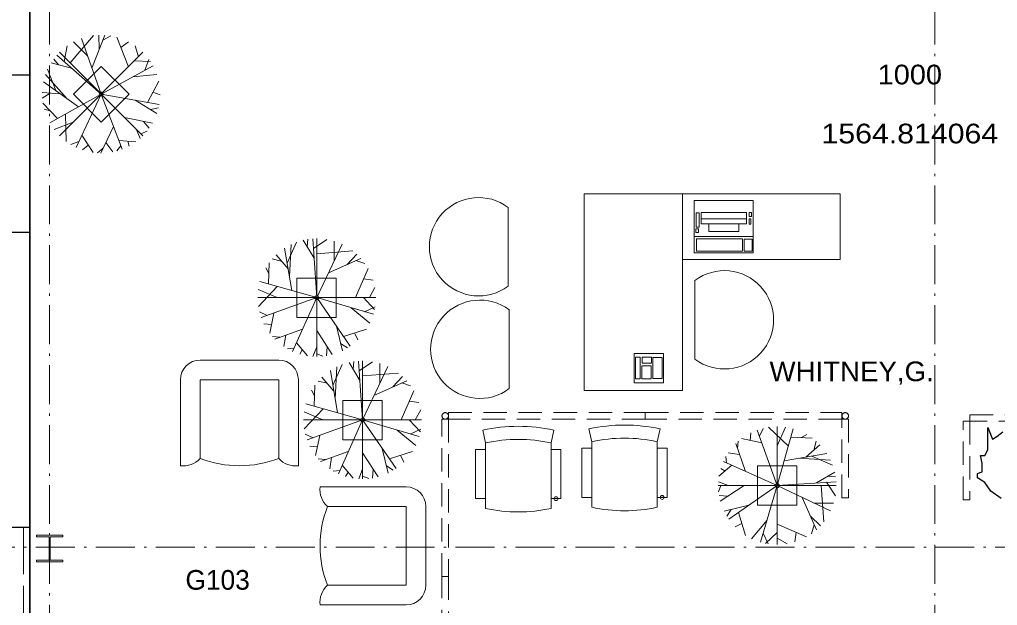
# Model space of a CAD drawing. Extents: x -118748 to -117136, y -118748 to -117596.
# Drawn here: x -118499.3 to -118260.7, y -118199 to -118056 of the extents above; entities that cross this region are included whole.
import ezdxf
from ezdxf.enums import TextEntityAlignment as Align

# ---------------------------------------------------------------- set-up
doc = ezdxf.new("R2010")
doc.units = 0
doc.header["$LTSCALE"] = 1.9
doc.header["$PDMODE"] = 32
doc.header["$PDSIZE"] = 0.95
for name, pattern in [('DOT_DASHED', [7.7, 5, -1.2, 0.3, -1.2]), ('LONG_DASHED', [7.5, 6, -1.5]), ('MEDIUM_DASHED', [4.5, 3, -1.5])]:
    doc.linetypes.add(name, pattern=pattern)
for name, color, linetype, lineweight in [('10', 7, 'DOT_DASHED', 13), ('12', 7, 'Continuous', 13), ('15', 7, 'Continuous', 13), ('16', 7, 'Continuous', 13), ('17', 7, 'Continuous', 25), ('20', 7, 'MEDIUM_DASHED', 13), ('23', 7, 'Continuous', 25), ('30', 7, 'Continuous', 13), ('4', 7, 'Continuous', 35), ('45', 7, 'Continuous', 25), ('5', 7, 'Continuous', 13), ('6', 7, 'Continuous', 13), ('60', 7, 'LONG_DASHED', 13), ('9', 7, 'Continuous', 35)]:
    doc.layers.add(name, color=color, linetype=linetype, lineweight=lineweight)
doc.layers.add('53', color=7, linetype='Continuous')

msp = doc.modelspace()

# ---------------------------------------------------------------- linework, layer by layer
at = {"layer": '10'}
for p, q in [((-118491.921, -117628.339), (-118491.921, -118698.41)), ((-118275.921, -117628.339), (-118275.921, -118698.41)), ((-118641.571, -118184.81), (-117285.521, -118184.81))]:
    msp.add_line(p, q, dxfattribs=at)
at = {"layer": '12'}
msp.add_lwpolyline([(-118495.104, -118188.362), (-118488.688, -118188.362), (-118488.688, -118187.966), (-118491.772, -118187.966), (-118491.772, -118182.262), (-118488.688, -118182.262), (-118488.688, -118181.866), (-118495.104, -118181.866), (-118495.104, -118182.262), (-118492.02, -118182.262), (-118492.02, -118187.966), (-118495.104, -118187.966)], close=True, dxfattribs=at)
at = {"layer": '15', "lineweight": 25}
for p, q in [((-118496.721, -118031.21), (-118496.721, -118069.61)), ((-118496.721, -118069.61), (-118506.321, -118069.61)), ((-118496.721, -118108.01), (-118506.321, -118108.01)), ((-118496.721, -118108.01), (-118496.721, -118180.01)), ((-118496.721, -118180.01), (-118586.321, -118180.01))]:
    msp.add_line(p, q, dxfattribs=at)
at = {"layer": '15'}
for p, q in [((-118380.049, -118101.88), (-118380.049, -118121.08)), ((-118334.488, -118138.921), (-118334.488, -118119.721)), ((-118379.768, -118126.911), (-118379.768, -118146.111)), ((-118436.026, -118139.148), (-118455.226, -118139.148)), ((-118460.026, -118143.948), (-118460.026, -118164.933)), ((-118431.226, -118164.933), (-118431.226, -118143.948)), ((-118385.586, -118159.364), (-118386.262, -118156.236)), ((-118369.586, -118159.364), (-118368.91, -118156.236)), ((-118359.666, -118159.062), (-118360.342, -118155.934)), ((-118343.666, -118159.062), (-118342.99, -118155.934)), ((-118385.586, -118175.364), (-118385.586, -118159.364)), ((-118369.586, -118175.364), (-118369.586, -118159.364)), ((-118359.666, -118175.062), (-118359.666, -118159.062)), ((-118343.666, -118175.062), (-118343.666, -118159.062)), ((-118387.986, -118172.964), (-118387.986, -118160.964)), ((-118385.586, -118160.964), (-118387.986, -118160.964)), ((-118385.586, -118172.964), (-118385.586, -118160.964)), ((-118369.586, -118172.964), (-118369.586, -118160.964)), ((-118367.186, -118160.964), (-118369.586, -118160.964)), ((-118367.186, -118172.964), (-118367.186, -118160.964)), ((-118362.066, -118172.662), (-118362.066, -118160.662)), ((-118359.666, -118160.662), (-118362.066, -118160.662)), ((-118359.666, -118172.662), (-118359.666, -118160.662)), ((-118343.666, -118172.662), (-118343.666, -118160.662)), ((-118341.266, -118160.662), (-118343.666, -118160.662)), ((-118341.266, -118172.662), (-118341.266, -118160.662)), ((-118404.942, -118170.1), (-118425.928, -118170.1)), ((-118387.986, -118172.964), (-118385.586, -118172.964)), ((-118369.586, -118172.964), (-118367.186, -118172.964)), ((-118362.066, -118172.662), (-118359.666, -118172.662)), ((-118343.666, -118172.662), (-118341.266, -118172.662)), ((-118400.142, -118194.1), (-118400.142, -118174.899)), ((-118425.928, -118198.899), (-118404.942, -118198.899))]:
    msp.add_line(p, q, dxfattribs=at)
for points in [[(-118361.487, -118146.556), (-118361.487, -118098.556), (-118337.487, -118098.556), (-118337.487, -118146.556)], [(-118337.487, -118114.556), (-118337.487, -118098.556), (-118299.087, -118098.556), (-118299.087, -118114.556)]]:
    msp.add_lwpolyline(points, close=True, dxfattribs=at)
for points in [[(-118436.026, -118163.148), (-118436.026, -118143.948), (-118455.226, -118143.948), (-118455.226, -118163.148)], [(-118424.142, -118194.1), (-118404.942, -118194.1), (-118404.942, -118174.899), (-118424.142, -118174.899)]]:
    msp.add_lwpolyline(points, dxfattribs=at)
for centre, radius, start, end in [((-118387.249, -118111.48), 12, 53.1301, 306.86989), ((-118327.288, -118129.321), 12, 233.1301, 126.86989), ((-118386.968, -118136.511), 12, 53.1301, 306.86989), ((-118455.226, -118143.948), 4.8, 90, 180), ((-118436.026, -118143.948), 4.8, 0, 90), ((-118351.666, -118196.07), 41.063, 77.80217, 102.19783), ((-118377.586, -118196.372), 41.063, 77.80217, 102.19783), ((-118377.586, -118196.372), 37.863, 77.80217, 102.19783), ((-118377.586, -118196.372), 37.863, 77.80217, 102.19783), ((-118351.666, -118196.07), 37.863, 77.80217, 102.19783), ((-118351.666, -118196.07), 37.863, 77.80217, 102.19783), ((-118459.331, -118159.456), 5.521, 262.77334, 318.03706), ((-118445.626, -118138.234), 26.699, 248.92678, 291.07322), ((-118431.92, -118159.456), 5.521, 221.96294, 277.22666), ((-118420.451, -118170.794), 5.521, 172.77334, 228.03706), ((-118404.942, -118174.899), 4.8, 0, 90), ((-118399.229, -118184.5), 26.699, 158.92678, 201.07322), ((-118377.586, -118138.355), 37.863, 257.80217, 282.19783), ((-118351.666, -118138.054), 37.863, 257.80217, 282.19783), ((-118420.451, -118198.205), 5.521, 131.96294, 187.22666), ((-118404.942, -118194.1), 4.8, 270, 0)]:
    msp.add_arc(centre, radius, start, end, dxfattribs=at)
for p in [(-118368.386, -118172.964), (-118342.466, -118172.662)]:
    msp.add_point(p, dxfattribs=at)
at = {"layer": '16'}
for p, q in [((-118496.721, -118069.61), (-118496.721, -118108.01)), ((-118334.638, -118109.006), (-118320.238, -118109.006))]:
    msp.add_line(p, q, dxfattribs=at)
for points in [[(-118334.638, -118113.006), (-118334.638, -118100.206), (-118320.238, -118100.206), (-118320.238, -118113.006)], [(-118334.18, -118106.724), (-118334.18, -118103.187), (-118333.473, -118103.187), (-118333.473, -118106.724)], [(-118332.974, -118104.685), (-118332.974, -118103.085), (-118321.865, -118103.085), (-118321.865, -118104.685)], [(-118332.974, -118105.891), (-118332.974, -118104.685), (-118321.865, -118104.685), (-118321.865, -118105.891)], [(-118321.24, -118103.104), (-118321.24, -118104.102), (-118320.658, -118104.102), (-118320.658, -118103.104)], [(-118321.24, -118104.685), (-118321.24, -118105.933), (-118320.824, -118105.933), (-118320.824, -118104.685)], [(-118334.263, -118107.972), (-118334.263, -118107.14), (-118333.598, -118107.14), (-118333.598, -118107.972)], [(-118331.06, -118107.764), (-118331.06, -118105.891), (-118323.737, -118105.891), (-118323.737, -118107.764)], [(-118334.097, -118109.553), (-118334.097, -118112.549), (-118322.905, -118112.549), (-118322.905, -118109.553)], [(-118322.489, -118109.636), (-118322.489, -118112.59), (-118320.492, -118112.59), (-118320.492, -118109.636)], [(-118349.334, -118144.712), (-118349.334, -118137.512), (-118342.134, -118137.512), (-118342.134, -118144.712)], [(-118347.878, -118143.706), (-118347.878, -118138.464), (-118348.959, -118138.464), (-118348.959, -118143.706)], [(-118347.378, -118138.464), (-118347.378, -118139.92), (-118345.09, -118139.92), (-118345.09, -118138.464)], [(-118347.461, -118140.585), (-118347.461, -118143.706), (-118345.173, -118143.706), (-118345.173, -118140.585)], [(-118344.715, -118138.547), (-118344.715, -118143.664), (-118342.51, -118143.664), (-118342.51, -118138.547)]]:
    msp.add_lwpolyline(points, close=True, dxfattribs=at)
at = {"layer": '17'}
msp.add_lwpolyline([(-118259.734, -118172.971), (-118262.268, -118171.161), (-118263.716, -118168.989), (-118265.526, -118167.902), (-118265.526, -118166.816), (-118264.44, -118166.454), (-118264.44, -118164.282), (-118264.802, -118162.472), (-118263.716, -118162.472), (-118262.992, -118161.024), (-118262.992, -118155.593), (-118261.906, -118158.489), (-118260.82, -118157.765), (-118259.372, -118156.679)], dxfattribs=at)
at = {"layer": '20'}
for points in [[(-118394.602, -118153.574), (-118394.602, -118151.974), (-118346.602, -118151.974), (-118346.602, -118153.574)], [(-118346.602, -118153.574), (-118346.602, -118151.974), (-118298.602, -118151.974), (-118298.602, -118153.574)], [(-118229.002, -118152.479), (-118229.002, -118154.079), (-118267.402, -118154.079), (-118267.402, -118152.479)], [(-118394.602, -118191.974), (-118396.202, -118191.974), (-118396.202, -118153.574), (-118394.602, -118153.574)], [(-118298.602, -118153.574), (-118297.002, -118153.574), (-118297.002, -118172.774), (-118298.602, -118172.774)], [(-118269.002, -118154.079), (-118267.402, -118154.079), (-118267.402, -118173.279), (-118269.002, -118173.279)], [(-118394.602, -118239.974), (-118396.202, -118239.974), (-118396.202, -118191.974), (-118394.602, -118191.974)]]:
    msp.add_lwpolyline(points, close=True, dxfattribs=at)
for centre in [(-118395.402, -118152.774), (-118297.802, -118152.774)]:
    msp.add_circle(centre, 0.8, dxfattribs=at)
at = {"layer": '23'}
for q in [(-118499.921, -118180.01), (-118496.721, -118292.01)]:
    msp.add_line((-118496.721, -118180.01), q, dxfattribs=at)
at = {"layer": '30'}
for p, q in [((-118486.922, -118066.624), (-118481.183, -118059.923)), ((-118482.657, -118064.878), (-118486.066, -118061.472)), ((-118479.34, -118074.205), (-118484.164, -118060.637)), ((-118481.589, -118067.882), (-118478.486, -118059.83)), ((-118479.805, -118063.252), (-118479.895, -118059.816)), ((-118478.964, -118061.071), (-118476.961, -118060.003)), ((-118472.672, -118067.537), (-118475.508, -118060.324)), ((-118474.507, -118062.869), (-118472.638, -118061.46)), ((-118469.158, -118084.387), (-118489.523, -118064.023)), ((-118489.523, -118084.387), (-118469.158, -118064.023)), ((-118488.407, -118066.282), (-118487.633, -118062.432)), ((-118470.263, -118065.128), (-118471.029, -118062.446)), ((-118486.575, -118067.883), (-118491.578, -118066.615)), ((-118489.76, -118067.076), (-118490.931, -118065.66)), ((-118479.34, -118074.205), (-118490.184, -118064.73)), ((-118471.277, -118066.142), (-118467.312, -118066.289)), ((-118468.697, -118068.422), (-118467.691, -118065.74)), ((-118490.411, -118073.354), (-118492.408, -118068.156)), ((-118479.34, -118074.205), (-118466.687, -118067.331)), ((-118484.847, -118077.294), (-118493.427, -118071.218)), ((-118487.716, -118075.262), (-118492.934, -118069.454)), ((-118471.615, -118070.008), (-118465.742, -118069.467)), ((-118468.016, -118076.28), (-118465.284, -118071.079)), ((-118489.227, -118074.192), (-118493.736, -118073.867)), ((-118491.774, -118074.008), (-118493.706, -118075.197)), ((-118466.707, -118073.788), (-118464.941, -118074.38)), ((-118490.037, -118080.206), (-118493.57, -118076.414)), ((-118479.34, -118074.205), (-118491.899, -118081.25)), ((-118479.34, -118074.205), (-118485.466, -118087.237)), ((-118479.34, -118074.205), (-118474.226, -118087.666)), ((-118479.34, -118074.205), (-118465.176, -118076.801)), ((-118471.049, -118075.724), (-118465.748, -118078.959)), ((-118491.807, -118078.305), (-118493.257, -118077.904)), ((-118467.288, -118078.019), (-118465.348, -118077.609)), ((-118486.186, -118081.051), (-118490.839, -118082.873)), ((-118488.074, -118079.104), (-118487.894, -118085.789)), ((-118473.635, -118079.91), (-118466.836, -118081.347)), ((-118469.02, -118080.885), (-118467.606, -118082.551)), ((-118476.327, -118082.136), (-118479.441, -118088.605)), ((-118470.846, -118082.699), (-118469.842, -118085.028)), ((-118469.629, -118083.916), (-118468.143, -118083.26)), ((-118484.798, -118085.816), (-118486.779, -118086.535)), ((-118484.066, -118084.258), (-118481.319, -118088.468)), ((-118475.038, -118085.527), (-118470.899, -118085.872)), ((-118472.826, -118085.711), (-118472.534, -118086.895)), ((-118482.48, -118086.688), (-118483.894, -118087.866)), ((-118478.876, -118087.431), (-118480.278, -118088.574)), ((-118478.214, -118086.054), (-118476.536, -118088.329)), ((-118474.529, -118086.869), (-118475.543, -118088.095)), ((-118429.072, -118111.484), (-118428.899, -118109.655)), ((-118426.745, -118123.893), (-118427.713, -118109.526)), ((-118427.554, -118111.88), (-118424.284, -118109.705)), ((-118426.745, -118138.293), (-118426.745, -118109.493)), ((-118432.823, -118122.184), (-118434.594, -118111.82)), ((-118433.972, -118115.463), (-118431.708, -118110.375)), ((-118433.415, -118118.718), (-118432.998, -118110.921)), ((-118427.391, -118114.307), (-118430.031, -118109.873)), ((-118426.745, -118123.893), (-118420.563, -118110.888)), ((-118422.495, -118114.953), (-118422.498, -118110.134)), ((-118435.398, -118114.962), (-118437.605, -118114.436)), ((-118433.727, -118116.893), (-118436.686, -118113.474)), ((-118426.745, -118113.172), (-118417.95, -118112.491)), ((-118423.864, -118117.832), (-118415.977, -118114.333)), ((-118419.329, -118115.82), (-118416.963, -118113.326)), ((-118438.46, -118117.977), (-118439.202, -118116.668)), ((-118438.552, -118120.572), (-118438.369, -118115.393)), ((-118417.315, -118123.893), (-118414.22, -118116.788)), ((-118417.192, -118114.872), (-118415.02, -118115.533)), ((-118415.312, -118119.295), (-118412.994, -118119.62)), ((-118436.385, -118121.182), (-118440.985, -118126.036)), ((-118426.745, -118123.893), (-118440.608, -118119.994)), ((-118413.908, -118123.893), (-118412.553, -118121.455)), ((-118441.145, -118123.893), (-118412.345, -118123.893)), ((-118436.427, -118123.893), (-118441.005, -118121.892)), ((-118426.745, -118123.893), (-118440.292, -118128.777)), ((-118426.745, -118123.893), (-118432.647, -118137.028)), ((-118426.745, -118123.893), (-118412.937, -118127.979)), ((-118426.745, -118123.893), (-118418.565, -118135.744)), ((-118415.342, -118123.893), (-118412.642, -118126.801)), ((-118418.314, -118126.388), (-118413.78, -118130.158)), ((-118415.13, -118127.33), (-118412.522, -118126.144)), ((-118438.815, -118128.244), (-118440.724, -118127.352)), ((-118437.195, -118127.66), (-118438.23, -118132.579)), ((-118437.793, -118130.5), (-118439.625, -118130.333)), ((-118421.957, -118130.83), (-118420.495, -118136.866)), ((-118435.769, -118133.573), (-118437.569, -118133.391)), ((-118430.222, -118131.632), (-118436.999, -118134.004)), ((-118434.327, -118133.068), (-118434.749, -118135.864)), ((-118426.745, -118131.961), (-118422.953, -118137.785)), ((-118420.205, -118133.368), (-118414.595, -118131.622)), ((-118417.517, -118132.532), (-118416.688, -118134.198)), ((-118431.709, -118134.941), (-118429.026, -118138.111)), ((-118426.745, -118135.905), (-118427.682, -118138.263)), ((-118424.172, -118135.914), (-118424.349, -118138.092)), ((-118420.92, -118135.112), (-118419.258, -118136.194)), ((-118432.298, -118136.25), (-118433.882, -118136.4)), ((-118430.275, -118136.636), (-118430.906, -118137.679)), ((-118426.745, -118137.626), (-118425.23, -118138.213)), ((-118422.802, -118145.322), (-118420.538, -118140.234)), ((-118422.245, -118148.577), (-118421.828, -118140.78)), ((-118416.221, -118144.165), (-118418.861, -118139.731)), ((-118417.902, -118141.343), (-118417.729, -118139.514)), ((-118415.575, -118153.751), (-118416.543, -118139.384)), ((-118416.384, -118141.738), (-118413.114, -118139.563)), ((-118415.575, -118168.152), (-118415.575, -118139.352)), ((-118415.575, -118153.751), (-118409.393, -118140.746)), ((-118411.325, -118144.811), (-118411.328, -118139.992)), ((-118421.653, -118152.042), (-118423.424, -118141.679)), ((-118415.575, -118143.03), (-118406.78, -118142.35)), ((-118408.159, -118145.679), (-118405.793, -118143.185)), ((-118427.382, -118150.431), (-118427.199, -118145.252)), ((-118424.228, -118144.821), (-118426.435, -118144.295)), ((-118422.557, -118146.751), (-118425.516, -118143.333)), ((-118412.694, -118147.69), (-118404.807, -118144.191)), ((-118406.022, -118144.731), (-118403.85, -118145.392)), ((-118427.29, -118147.835), (-118428.032, -118146.527)), ((-118406.145, -118153.751), (-118403.05, -118146.647)), ((-118415.575, -118153.751), (-118429.438, -118149.853)), ((-118404.142, -118149.153), (-118401.824, -118149.479)), ((-118425.257, -118153.751), (-118429.836, -118151.75)), ((-118425.215, -118151.04), (-118429.815, -118155.895)), ((-118402.738, -118153.751), (-118401.383, -118151.313)), ((-118429.975, -118153.751), (-118401.175, -118153.751)), ((-118415.575, -118153.751), (-118429.122, -118158.635)), ((-118415.575, -118153.751), (-118421.477, -118166.887)), ((-118415.575, -118153.751), (-118401.767, -118157.838)), ((-118415.575, -118153.751), (-118407.395, -118165.602)), ((-118404.173, -118153.751), (-118401.472, -118156.659)), ((-118427.645, -118158.103), (-118429.554, -118157.21)), ((-118426.025, -118157.519), (-118427.06, -118162.438)), ((-118407.144, -118156.246), (-118402.61, -118160.017)), ((-118403.96, -118157.189), (-118401.352, -118156.003)), ((-118321.002, -118158.744), (-118320.835, -118156.911)), ((-118314.396, -118169.791), (-118319.279, -118156.245)), ((-118318.747, -118157.722), (-118317.854, -118155.813)), ((-118311.684, -118160.152), (-118316.539, -118155.552)), ((-118314.396, -118155.391), (-118314.396, -118184.191)), ((-118314.396, -118160.11), (-118312.394, -118155.531)), ((-118314.396, -118169.791), (-118310.497, -118155.929)), ((-118308.479, -118158.076), (-118307.171, -118157.335)), ((-118322.134, -118166.314), (-118324.506, -118159.538)), ((-118324.076, -118160.767), (-118323.893, -118158.967)), ((-118318.163, -118159.342), (-118323.082, -118158.306)), ((-118311.075, -118157.984), (-118305.896, -118158.168)), ((-118307.395, -118162.809), (-118303.977, -118159.851)), ((-118305.465, -118161.139), (-118304.939, -118158.932)), ((-118426.623, -118160.358), (-118428.455, -118160.191)), ((-118419.052, -118161.49), (-118425.829, -118163.862)), ((-118415.575, -118161.82), (-118411.783, -118167.643)), ((-118410.787, -118160.689), (-118409.325, -118166.724)), ((-118409.035, -118163.227), (-118403.425, -118161.48)), ((-118323.571, -118162.209), (-118326.366, -118161.787)), ((-118312.686, -118163.713), (-118302.323, -118161.942)), ((-118424.599, -118163.432), (-118426.399, -118163.249)), ((-118423.157, -118162.927), (-118423.579, -118165.722)), ((-118406.347, -118162.39), (-118405.518, -118164.057)), ((-118314.396, -118169.791), (-118327.531, -118163.889)), ((-118326.753, -118164.239), (-118326.903, -118162.655)), ((-118309.221, -118163.121), (-118301.424, -118163.539)), ((-118305.966, -118162.565), (-118300.878, -118164.829)), ((-118421.128, -118166.109), (-118422.712, -118166.259)), ((-118420.539, -118164.8), (-118417.856, -118167.97)), ((-118419.105, -118166.494), (-118419.736, -118167.537)), ((-118415.575, -118165.764), (-118416.512, -118168.121)), ((-118413.001, -118165.772), (-118413.179, -118167.951)), ((-118409.75, -118164.971), (-118408.088, -118166.052)), ((-118325.444, -118164.827), (-118328.614, -118167.511)), ((-118327.138, -118166.262), (-118328.182, -118165.631)), ((-118304.809, -118169.146), (-118300.376, -118166.505)), ((-118415.575, -118167.485), (-118414.06, -118168.072)), ((-118326.408, -118169.791), (-118328.765, -118168.855)), ((-118314.396, -118169.791), (-118300.028, -118168.824)), ((-118302.382, -118168.982), (-118300.208, -118172.252)), ((-118301.987, -118167.465), (-118300.158, -118167.637)), ((-118328.796, -118169.791), (-118299.996, -118169.791)), ((-118328.129, -118169.791), (-118328.716, -118171.306)), ((-118322.464, -118169.791), (-118328.287, -118173.583)), ((-118314.396, -118169.791), (-118326.247, -118177.971)), ((-118314.396, -118169.791), (-118318.482, -118183.599)), ((-118314.396, -118169.791), (-118301.39, -118175.974)), ((-118303.674, -118169.791), (-118302.994, -118178.587)), ((-118326.417, -118172.365), (-118328.595, -118172.188)), ((-118308.335, -118172.673), (-118304.836, -118180.56)), ((-118305.456, -118174.041), (-118300.636, -118174.039)), ((-118321.333, -118174.58), (-118327.369, -118176.041)), ((-118325.615, -118175.617), (-118326.696, -118177.278)), ((-118323.871, -118176.332), (-118322.124, -118181.941)), ((-118323.034, -118179.019), (-118324.701, -118179.849)), ((-118316.891, -118178.222), (-118320.661, -118182.757)), ((-118306.323, -118177.208), (-118303.829, -118179.574)), ((-118317.833, -118181.407), (-118316.647, -118184.014)), ((-118314.396, -118181.194), (-118317.304, -118183.895)), ((-118314.396, -118179.222), (-118307.291, -118182.316)), ((-118309.797, -118181.225), (-118310.123, -118183.543)), ((-118305.375, -118179.345), (-118306.036, -118181.516)), ((-118314.396, -118182.628), (-118311.957, -118183.983))]:
    msp.add_line(p, q, dxfattribs=at)
for points in [[(-118479.337, -118081.058), (-118486.125, -118074.27), (-118479.337, -118067.481), (-118472.549, -118074.27)], [(-118431.589, -118128.741), (-118431.589, -118119.141), (-118421.989, -118119.141), (-118421.989, -118128.741)], [(-118420.419, -118158.6), (-118420.419, -118149), (-118410.819, -118149), (-118410.819, -118158.6)], [(-118319.244, -118164.948), (-118309.644, -118164.948), (-118309.644, -118174.548), (-118319.244, -118174.548)]]:
    msp.add_lwpolyline(points, close=True, dxfattribs=at)
for p in [(-118479.34, -118074.205), (-118426.745, -118123.893), (-118415.575, -118153.751), (-118314.396, -118169.791)]:
    msp.add_point(p, dxfattribs=at)
at = {"layer": '4'}
msp.add_lwpolyline([(-118496.721, -117964.01), (-118496.721, -118636.01), (-118271.121, -118636.01), (-118271.121, -118588.01), (-118115.969, -118588.01), (-118106.1, -118586.234), (-118096.66, -118581.314), (-118089.115, -118573.804), (-118084.156, -118564.399), (-118081.154, -118548.633), (-118079.134, -118548.633), (-117884.057, -118548.587), (-117881.646, -118565.336), (-117876.897, -118574.111), (-117869.271, -118581.538), (-117859.789, -118586.351), (-117850.271, -118588.01), (-117695.121, -118588.01), (-117695.121, -118636.01), (-117469.521, -118636.01), (-117469.521, -117964.01)], close=True, dxfattribs=at)
at = {"layer": '5'}
for points in [[(-118115.969, -118588.01), (-118271.121, -118588.01), (-118271.121, -118636.01), (-118496.721, -118636.01), (-118496.721, -117964.01)], [(-118126.371, -118184.81), (-118126.371, -118292.01), (-118463.121, -118292.01), (-118496.721, -118292.01), (-118496.721, -118180.01), (-118496.721, -117964.01)]]:
    msp.add_lwpolyline(points, dxfattribs=at)
at = {"layer": '6'}
msp.add_lwpolyline([(-118126.371, -118184.81), (-118126.371, -118292.01), (-118496.721, -118292.01), (-118496.721, -117964.01)], dxfattribs=at)
at = {"layer": '60'}
msp.add_line((-118498.321, -118180.01), (-118498.321, -118343.21), dxfattribs=at)

# ---------------------------------------------------------------- texts
at = {"layer": '45'}
for s, width, p in [('1000', 1.1, (-118282.052, -118071.848)), ('1564.814064', 1.15, (-118282.052, -118086.248))]:
    msp.add_text(s, height=4.8, dxfattribs=dict(at, width=width)).set_placement(p, align=Align.CENTER)
at = {"layer": '53', "width": 1.05}
msp.add_text('WHITNEY,G.', height=4.8, dxfattribs=at).set_placement((-118316.283, -118144.293))
at = {"layer": '9'}
msp.add_text('G103', height=4.8, dxfattribs=at).set_placement((-118450.934, -118195.196), align=Align.CENTER)

doc.saveas('drawing.dxf')
